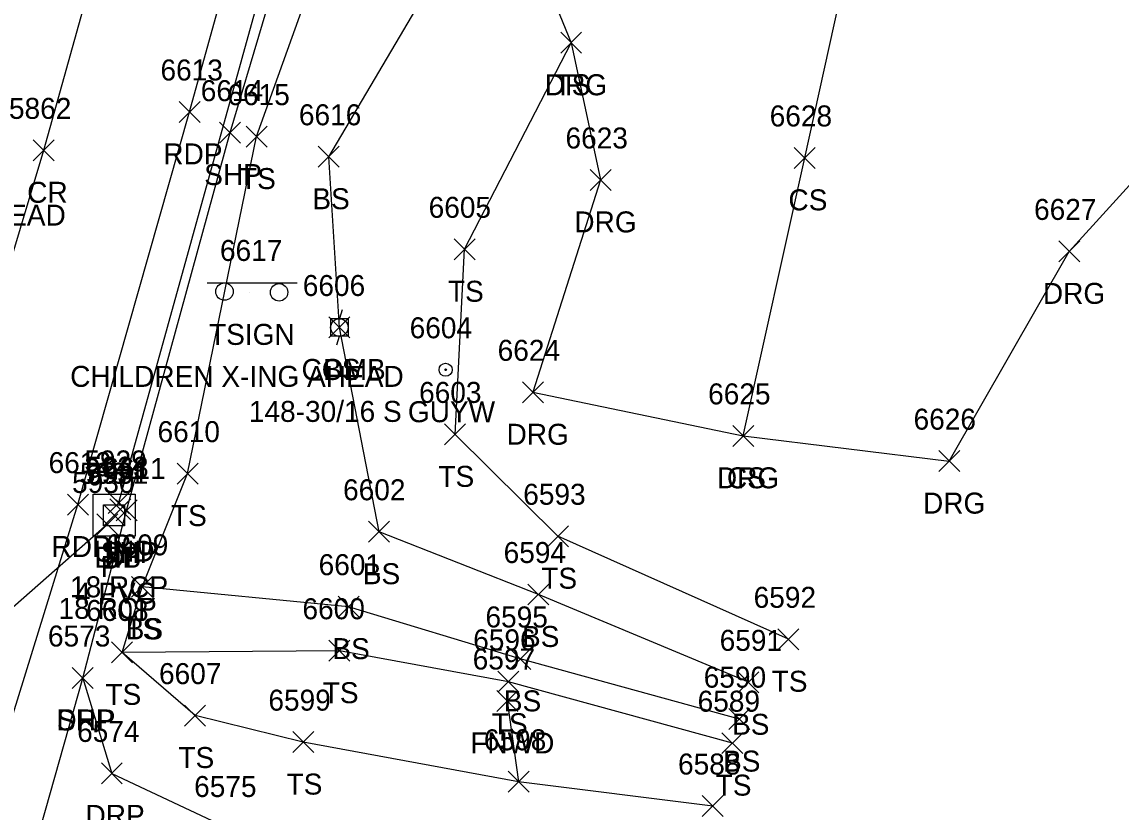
# Model space of a CAD drawing. Extents: x 1443912 to 1445411, y 621446 to 623693.
# Drawn here: x 1444674.1 to 1444778.9, y 622248.9 to 622324.2 of the extents above; entities that cross this region are included whole.
import ezdxf

# ---------------------------------------------------------------- set-up
doc = ezdxf.new("R2010")
doc.units = 0
for name, color, linetype in [('D_A', 7, 'Continuous'), ('D_C', 7, 'Continuous'), ('D_I', 7, 'Continuous'), ('D_TIC', 7, 'Continuous'), ('DCP', 7, 'Continuous'), ('DS', 7, 'Continuous'), ('L_A', 7, 'Continuous'), ('L_I', 7, 'Continuous'), ('L_TIC', 7, 'Continuous'), ('LELB', 7, 'Continuous'), ('LFNC', 7, 'Continuous'), ('P_A', 7, 'Continuous'), ('P_I', 7, 'Continuous'), ('P_TIC', 7, 'Continuous'), ('PET', 7, 'Continuous'), ('PRC', 7, 'Continuous'), ('PSP', 7, 'Continuous'), ('R_A', 7, 'Continuous'), ('R_I', 7, 'Continuous'), ('R_TIC', 7, 'Continuous'), ('RDG', 7, 'Continuous'), ('RDP', 7, 'Continuous'), ('S_A', 7, 'Continuous'), ('S_C', 7, 'Continuous'), ('S_I', 7, 'Continuous'), ('SSGN', 7, 'Continuous'), ('U_A', 7, 'Continuous'), ('U_C', 7, 'Continuous'), ('U_I', 7, 'Continuous'), ('UP', 7, 'Continuous'), ('UPGW', 7, 'Continuous')]:
    doc.layers.add(name, color=color, linetype=linetype)

msp = doc.modelspace()

# ---------------------------------------------------------------- linework, layer by layer
at = {"layer": 'D_TIC'}
for points in [[(1444682.32, 622277.32), (1444684.32, 622279.32)], [(1444684.32, 622277.32), (1444682.32, 622279.32)], [(1444682.49, 622276.72), (1444684.49, 622278.72)], [(1444684.49, 622276.72), (1444682.49, 622278.72)], [(1444681.9, 622276.14), (1444683.9, 622278.14)], [(1444683.9, 622276.14), (1444681.9, 622278.14)], [(1444681.23, 622275.27), (1444683.23, 622277.27)], [(1444683.23, 622275.27), (1444681.23, 622277.27)]]:
    msp.add_lwpolyline(points, dxfattribs=at)
at = {"layer": 'DCP'}
for points in [[(1444737.15, 622472.26), (1444683.32, 622278.32)], [(1444682.23, 622276.27), (1444625.81, 622226.66)]]:
    msp.add_lwpolyline(points, dxfattribs=at)
at = {"layer": 'DS'}
for p, q in [((1444680.89, 622279.15), (1444684.89, 622279.15)), ((1444680.89, 622275.15), (1444680.89, 622279.15)), ((1444684.89, 622279.15), (1444684.89, 622275.15)), ((1444681.89, 622276.15), (1444681.89, 622278.15)), ((1444681.89, 622278.15), (1444683.89, 622278.15)), ((1444683.89, 622278.15), (1444683.89, 622276.15)), ((1444682.89, 622277.15), (1444682.89, 622277.15)), ((1444682.89, 622277.15), (1444682.89, 622277.15)), ((1444683.89, 622276.15), (1444681.89, 622276.15)), ((1444684.89, 622275.15), (1444680.89, 622275.15))]:
    msp.add_line(p, q, dxfattribs=at)
at = {"layer": 'L_TIC'}
for points in [[(1444725.47, 622321.17), (1444727.47, 622323.17)], [(1444727.47, 622321.17), (1444725.47, 622323.17)], [(1444695.48, 622312.23), (1444697.48, 622314.23)], [(1444697.48, 622312.23), (1444695.48, 622314.23)], [(1444702.35, 622310.31), (1444704.35, 622312.31)], [(1444704.35, 622310.31), (1444702.35, 622312.31)], [(1444747.75, 622310.2), (1444749.75, 622312.2)], [(1444749.75, 622310.2), (1444747.75, 622312.2)], [(1444715.31, 622301.49), (1444717.31, 622303.49)], [(1444717.31, 622301.49), (1444715.31, 622303.49)], [(1444703.37, 622294.04), (1444705.37, 622296.04)], [(1444705.37, 622294.04), (1444703.37, 622296.04)], [(1444714.4, 622283.85), (1444716.4, 622285.85)], [(1444716.4, 622283.85), (1444714.4, 622285.85)], [(1444741.88, 622283.71), (1444743.88, 622285.71)], [(1444743.88, 622283.71), (1444741.88, 622285.71)], [(1444688.9, 622280.11), (1444690.9, 622282.11)], [(1444690.9, 622280.11), (1444688.9, 622282.11)], [(1444707.16, 622274.57), (1444709.16, 622276.57)], [(1444709.16, 622274.57), (1444707.16, 622276.57)], [(1444724.21, 622274.14), (1444726.21, 622276.14)], [(1444726.21, 622274.14), (1444724.21, 622276.14)], [(1444684.55, 622269.32), (1444686.55, 622271.32)], [(1444686.55, 622269.32), (1444684.55, 622271.32)], [(1444684.55, 622269.32), (1444686.55, 622271.32)], [(1444686.55, 622269.32), (1444684.55, 622271.32)], [(1444722.34, 622268.59), (1444724.34, 622270.59)], [(1444724.34, 622268.59), (1444722.34, 622270.59)], [(1444704.25, 622267.43), (1444706.25, 622269.43)], [(1444706.25, 622267.43), (1444704.25, 622269.43)], [(1444746.18, 622264.32), (1444748.18, 622266.32)], [(1444748.18, 622264.32), (1444746.18, 622266.32)], [(1444682.65, 622263.07), (1444684.65, 622265.07)], [(1444684.65, 622263.07), (1444682.65, 622265.07)], [(1444682.65, 622263.07), (1444684.65, 622265.07)], [(1444684.65, 622263.07), (1444682.65, 622265.07)], [(1444703.37, 622263.23), (1444705.37, 622265.23)], [(1444705.37, 622263.23), (1444703.37, 622265.23)], [(1444720.61, 622262.45), (1444722.61, 622264.45)], [(1444722.61, 622262.45), (1444720.61, 622264.45)], [(1444719.49, 622260.27), (1444721.49, 622262.27)], [(1444721.49, 622260.27), (1444719.49, 622262.27)], [(1444742.37, 622260.22), (1444744.37, 622262.22)], [(1444744.37, 622260.22), (1444742.37, 622262.22)], [(1444719.38, 622258.44), (1444721.38, 622260.44)], [(1444721.38, 622258.44), (1444719.38, 622260.44)], [(1444689.61, 622257.05), (1444691.61, 622259.05)], [(1444691.61, 622257.05), (1444689.61, 622259.05)], [(1444741.51, 622256.71), (1444743.51, 622258.71)], [(1444743.51, 622256.71), (1444741.51, 622258.71)], [(1444699.92, 622254.52), (1444701.92, 622256.52)], [(1444701.92, 622254.52), (1444699.92, 622256.52)], [(1444740.84, 622254.42), (1444742.84, 622256.42)], [(1444742.84, 622254.42), (1444740.84, 622256.42)], [(1444720.46, 622250.74), (1444722.46, 622252.74)], [(1444722.46, 622250.74), (1444720.46, 622252.74)], [(1444720.46, 622250.74), (1444722.46, 622252.74)], [(1444722.46, 622250.74), (1444720.46, 622252.74)], [(1444738.97, 622248.43), (1444740.97, 622250.43)], [(1444740.97, 622248.43), (1444738.97, 622250.43)]]:
    msp.add_lwpolyline(points, dxfattribs=at)
at = {"layer": 'LELB'}
for points in [[(1444742.88, 622284.71), (1444748.75, 622311.2), (1444753.94, 622334.73), (1444744.93, 622339.22), (1444726.6, 622359.05), (1444735.05, 622388.08), (1444756.32, 622435.36), (1444757.96, 622467.34), (1444762.58, 622493), (1444774.84, 622527.33), (1444774.74, 622549.75)], [(1444739.97, 622249.43), (1444721.46, 622251.74), (1444700.92, 622255.52), (1444690.61, 622258.05), (1444683.65, 622264.07), (1444685.55, 622270.32), (1444689.9, 622281.11), (1444696.48, 622313.23), (1444707.7, 622344.5), (1444714.14, 622363.56), (1444716.18, 622385.71), (1444728.96, 622432.31), (1444739.26, 622468.67), (1444740.51, 622472.1), (1444740.52, 622475.28)], [(1444743.37, 622261.22), (1444723.34, 622269.59), (1444708.16, 622275.57), (1444704.37, 622295.04), (1444703.35, 622311.31), (1444719.64, 622338.88)], [(1444747.18, 622265.32), (1444725.21, 622275.14), (1444715.4, 622284.85), (1444716.31, 622302.49), (1444726.47, 622322.17)], [(1444742.51, 622257.71), (1444721.61, 622263.45), (1444705.25, 622268.43), (1444685.55, 622270.32)], [(1444741.84, 622255.42), (1444720.49, 622261.27), (1444704.37, 622264.23), (1444683.65, 622264.07)]]:
    msp.add_lwpolyline(points, dxfattribs=at)
at = {"layer": 'LFNC'}
msp.add_lwpolyline([(1444720.38, 622259.44), (1444721.46, 622251.74)], dxfattribs=at)
at = {"layer": 'P_TIC'}
for points in [[(1444689.09, 622314.58), (1444691.09, 622316.58)], [(1444691.09, 622314.58), (1444689.09, 622316.58)], [(1444692.94, 622312.61), (1444694.94, 622314.61)], [(1444694.94, 622312.61), (1444692.94, 622314.61)], [(1444675.17, 622310.92), (1444677.17, 622312.92)], [(1444677.17, 622310.92), (1444675.17, 622312.92)], [(1444678.43, 622277.16), (1444680.43, 622279.16)], [(1444680.43, 622277.16), (1444678.43, 622279.16)], [(1444683.08, 622276.6), (1444685.08, 622278.6)], [(1444685.08, 622276.6), (1444683.08, 622278.6)], [(1444678.89, 622260.63), (1444680.89, 622262.63)], [(1444680.89, 622260.63), (1444678.89, 622262.63)]]:
    msp.add_lwpolyline(points, dxfattribs=at)
at = {"layer": 'PET'}
msp.add_lwpolyline([(1444623.48, 622089.5), (1444632.2, 622118.09), (1444643.37, 622155.41), (1444656.28, 622199.74), (1444664.4, 622229.62), (1444679.43, 622278.16), (1444690.09, 622315.58), (1444698.44, 622345.72), (1444710.36, 622388.15), (1444723.31, 622433.67), (1444734.7, 622474.11), (1444754.07, 622543.94), (1444762.27, 622574.66), (1444773.16, 622611.58)], dxfattribs=at)
at = {"layer": 'PRC'}
msp.add_lwpolyline([(1444864.1, 623005.34), (1444851.39, 622950.16), (1444837.25, 622893.61), (1444822.84, 622838.02), (1444810.34, 622792.94), (1444799.32, 622750.35), (1444788.05, 622712.65), (1444779.51, 622680.27), (1444771.55, 622651.63), (1444762.01, 622615.65), (1444752.75, 622584.12), (1444739.92, 622538.84), (1444733.6, 622516.91), (1444722.13, 622475.76), (1444713.59, 622446.41), (1444702.09, 622404.55), (1444689.87, 622361.08), (1444676.17, 622311.92), (1444657.59, 622249.98), (1444643.66, 622204.01), (1444635.38, 622177.66), (1444620.59, 622126.88), (1444604.97, 622075.74)], dxfattribs=at)
at = {"layer": 'PSP'}
msp.add_lwpolyline([(1444628.13, 622076.36), (1444639.3, 622115.36), (1444644.89, 622137.62), (1444649.21, 622153.55), (1444661.8, 622198.05), (1444670.3, 622227.5), (1444674.58, 622242.76), (1444679.89, 622261.63), (1444684.08, 622277.6), (1444693.94, 622313.61), (1444703.2, 622344.72), (1444709.19, 622365.83), (1444714.84, 622387.4), (1444727.7, 622432.5), (1444737.82, 622469.76), (1444738.76, 622472.58), (1444739.4, 622474.95), (1444744.7, 622495.27), (1444757.04, 622537.24), (1444773.11, 622588.76)], dxfattribs=at)
at = {"layer": 'R_TIC'}
for points in [[(1444725.47, 622321.17), (1444727.47, 622323.17)], [(1444727.47, 622321.17), (1444725.47, 622323.17)], [(1444728.28, 622308.1), (1444730.28, 622310.1)], [(1444730.28, 622308.1), (1444728.28, 622310.1)], [(1444772.96, 622301.29), (1444774.96, 622303.29)], [(1444774.96, 622301.29), (1444772.96, 622303.29)], [(1444721.82, 622287.86), (1444723.82, 622289.86)], [(1444723.82, 622287.86), (1444721.82, 622289.86)], [(1444741.88, 622283.71), (1444743.88, 622285.71)], [(1444743.88, 622283.71), (1444741.88, 622285.71)], [(1444761.53, 622281.3), (1444763.53, 622283.3)], [(1444763.53, 622281.3), (1444761.53, 622283.3)], [(1444678.89, 622260.63), (1444680.89, 622262.63)], [(1444680.89, 622260.63), (1444678.89, 622262.63)], [(1444681.67, 622251.54), (1444683.67, 622253.54)], [(1444683.67, 622251.54), (1444681.67, 622253.54)]]:
    msp.add_lwpolyline(points, dxfattribs=at)
at = {"layer": 'RDG'}
msp.add_lwpolyline([(1444703.2, 622344.72), (1444707.7, 622344.5), (1444719.64, 622338.88), (1444726.47, 622322.17), (1444729.28, 622309.1), (1444722.82, 622288.86), (1444742.88, 622284.71), (1444762.53, 622282.3), (1444773.96, 622302.29), (1444789.67, 622319.53), (1444800.48, 622324.69)], dxfattribs=at)
at = {"layer": 'RDP'}
msp.add_lwpolyline([(1444679.89, 622261.63), (1444682.67, 622252.54), (1444693.82, 622247.29), (1444711.52, 622242.43)], dxfattribs=at)
at = {"layer": 'SSGN'}
for p, q in [((1444691.75, 622299.3), (1444700.34, 622299.3)), ((1444695.77, 622298.39), (1444695.77, 622298.39))]:
    msp.add_line(p, q, dxfattribs=at)
for centre in [(1444693.41, 622298.46), (1444698.62, 622298.39)]:
    msp.add_circle(centre, 0.833, dxfattribs=at)
at = {"layer": 'UP'}
for p, q in [((1444704.62, 622296.71), (1444704.37, 622295.88)), ((1444703.54, 622294.21), (1444703.54, 622295.88)), ((1444703.54, 622295.88), (1444705.2, 622295.88)), ((1444705.2, 622295.88), (1444705.2, 622294.21)), ((1444704.37, 622295.04), (1444704.37, 622295.04)), ((1444705.2, 622294.21), (1444703.54, 622294.21)), ((1444704.12, 622293.38), (1444704.37, 622294.21))]:
    msp.add_line(p, q, dxfattribs=at)
msp.add_circle((1444704.37, 622295.04), 0.833, dxfattribs=at)
at = {"layer": 'UPGW'}
for radius in [0.625, 0.0833]:
    msp.add_circle((1444714.5, 622291.01), radius, dxfattribs=at)

# ---------------------------------------------------------------- texts
at = {"layer": 'D_A'}
for s, p in [('UND', (1444680.96, 622272.72)), ('P', (1444682.69, 622273.32)), ('DIB', (1444681, 622272.14)), ('DI', (1444681.95, 622272.15)), ('P', (1444681.6, 622271.27))]:
    msp.add_text(s, height=2, dxfattribs=at).set_placement(p)
at = {"layer": 'D_C'}
for s, p in [('18 RCP', (1444678.68, 622269.32)), ('4 PVC', (1444679.15, 622268.72)), ('18 RCP', (1444677.59, 622267.27))]:
    msp.add_text(s, height=2, dxfattribs=at).set_placement(p)
at = {"layer": 'D_I'}
for s, p in [('5929', (1444680.05, 622281.32)), ('5933', (1444680.23, 622280.72)), ('5934', (1444679.63, 622280.15)), ('5931', (1444680.21, 622280.14)), ('5930', (1444678.88, 622279.27))]:
    msp.add_text(s, height=2, dxfattribs=at).set_placement(p)
at = {"layer": 'L_A'}
for s, p in [('TS', (1444724.88, 622317.17)), ('TS', (1444694.89, 622308.23)), ('BS', (1444701.79, 622306.31)), ('CS', (1444747.19, 622306.2)), ('TS', (1444714.72, 622297.49)), ('BS', (1444702.81, 622290.04)), ('TS', (1444713.81, 622279.85)), ('CS', (1444741.32, 622279.71)), ('TS', (1444688.31, 622276.11)), ('BS', (1444706.6, 622270.57)), ('TS', (1444723.62, 622270.14)), ('TS', (1444683.96, 622265.32)), ('BS', (1444683.99, 622265.32)), ('BS', (1444721.78, 622264.59)), ('BS', (1444703.7, 622263.43)), ('TS', (1444745.59, 622260.32)), ('TS', (1444682.06, 622259.07)), ('TS', (1444682.06, 622259.07)), ('TS', (1444702.78, 622259.23)), ('BS', (1444720.05, 622258.45)), ('TS', (1444718.9, 622256.27)), ('BS', (1444741.81, 622256.22)), ('FNWD', (1444716.85, 622254.44)), ('TS', (1444689.02, 622253.05)), ('BS', (1444740.95, 622252.71)), ('TS', (1444699.33, 622250.52)), ('TS', (1444740.25, 622250.42))]:
    msp.add_text(s, height=2, dxfattribs=at).set_placement(p)
at = {"layer": 'L_I'}
for s, p in [('6615', (1444693.69, 622316.23)), ('6616', (1444700.51, 622314.31)), ('6628', (1444745.4, 622314.2)), ('6605', (1444712.88, 622305.49)), ('6606', (1444700.88, 622298.04)), ('6603', (1444711.97, 622287.85)), ('6625', (1444739.53, 622287.71)), ('6610', (1444687.03, 622284.11)), ('6602', (1444704.72, 622278.57)), ('6593', (1444721.9, 622278.14)), ('6609', (1444682.11, 622273.32)), ('6609', (1444682.11, 622273.32)), ('6594', (1444720.03, 622272.59)), ('6601', (1444702.39, 622271.43)), ('6592', (1444743.87, 622268.32)), ('6600', (1444700.85, 622267.23)), ('6608', (1444680.22, 622267.07)), ('6608', (1444680.22, 622267.07)), ('6595', (1444718.3, 622266.45)), ('6596', (1444717.13, 622264.27)), ('6591', (1444740.63, 622264.22)), ('6597', (1444717.08, 622262.44)), ('6607', (1444687.17, 622261.05)), ('6590', (1444739.11, 622260.71)), ('6599', (1444697.6, 622258.52)), ('6589', (1444738.53, 622258.42)), ('6598', (1444718.15, 622254.74)), ('6598', (1444718.15, 622254.74)), ('6588', (1444736.66, 622252.43)), ('6575', (1444690.52, 622250.29))]:
    msp.add_text(s, height=2, dxfattribs=at).set_placement(p)
at = {"layer": 'P_A'}
for s, p in [('RDP', (1444687.58, 622310.58)), ('SHP', (1444691.48, 622308.61)), ('CR', (1444674.6, 622306.92)), ('RDP', (1444676.92, 622273.16)), ('SHP', (1444681.61, 622272.6)), ('SHP', (1444677.43, 622256.63))]:
    msp.add_text(s, height=2, dxfattribs=at).set_placement(p)
at = {"layer": 'P_I'}
for s, p in [('6613', (1444687.31, 622318.58)), ('6614', (1444691.15, 622316.61)), ('5862', (1444672.86, 622314.92)), ('6612', (1444676.64, 622281.16)), ('6611', (1444681.86, 622280.6)), ('6573', (1444676.58, 622264.63))]:
    msp.add_text(s, height=2, dxfattribs=at).set_placement(p)
at = {"layer": 'R_A'}
for s, p in [('DRG', (1444723.96, 622317.17)), ('DRG', (1444726.77, 622304.1)), ('DRG', (1444771.45, 622297.29)), ('DRG', (1444720.31, 622283.86)), ('DRG', (1444740.37, 622279.71)), ('DRG', (1444760.02, 622277.3)), ('DRP', (1444677.38, 622256.63)), ('DRP', (1444680.16, 622247.54))]:
    msp.add_text(s, height=2, dxfattribs=at).set_placement(p)
at = {"layer": 'R_I'}
for s, p in [('6623', (1444725.93, 622312.1)), ('6627', (1444770.61, 622305.29)), ('6624', (1444719.46, 622291.86)), ('6625', (1444739.53, 622287.71)), ('6626', (1444759.12, 622285.3)), ('6573', (1444676.58, 622264.63)), ('6574', (1444679.36, 622255.54)), ('6575', (1444690.52, 622250.29))]:
    msp.add_text(s, height=2, dxfattribs=at).set_placement(p)
at = {"layer": 'S_A'}
msp.add_text('TSIGN', height=2, dxfattribs=at).set_placement((1444691.94, 622293.38))
at = {"layer": 'S_C'}
msp.add_text('CHILDREN X-ING AHEAD', height=2, dxfattribs=at).set_placement((1444678.7, 622289.38))
at = {"layer": 'S_I'}
msp.add_text('6617', height=2, dxfattribs=at).set_placement((1444692.98, 622301.38))
at = {"layer": 'U_A'}
for s, p in [('OVERHEAD', (1444663.27, 622304.75)), ('COMB', (1444700.76, 622290.04)), ('GUYW', (1444710.9, 622286.01))]:
    msp.add_text(s, height=2, dxfattribs=at).set_placement(p)
at = {"layer": 'U_C'}
msp.add_text('148-30/16 S', height=2, dxfattribs=at).set_placement((1444695.74, 622286.04))
at = {"layer": 'U_I'}
for s, p in [('6606', (1444700.88, 622298.04)), ('6604', (1444711.07, 622294.01))]:
    msp.add_text(s, height=2, dxfattribs=at).set_placement(p)

doc.saveas('drawing.dxf')
